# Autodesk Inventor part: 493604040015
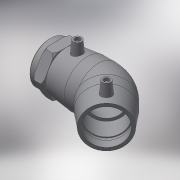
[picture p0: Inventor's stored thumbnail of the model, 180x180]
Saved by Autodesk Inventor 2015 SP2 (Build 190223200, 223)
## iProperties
Created: 2017-06
Part Number: 493604040015
Material: Generic
Description: PLASSON 45° ELBOW TRANSITION FEMALE 40-1.1/2"
Document SubType Name: Modeling
Designer: KIM
Mass: 179.754 g
Surface Area: 478.427 cm^2
Volume: 179.754 cm^3
Density: 1 g/cm^3
Appearance: Default
Author: KIM
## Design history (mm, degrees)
derived "493604.ipt"
feature "Solid1::493604.ipt"
tag "TaggingFeature1"
body "Solid1"
other parameters: "d2" = 56, "d4" = 27, "d5" = 50.4, "d8" = 168 deg, "d10" = 17.6, "d11" = 5.86667, "d29" = 47, "d30" = 15, "d31" = 37.8, "d34" = 5 deg, "d41" = 4, "d42" = 14, "d43" = 0, "d50" = 34, "d51" = 17.6, "d52" = 44, "d54" = 135 deg, "d86" = 25.2, "d87" = 135 deg, "d88" = 108, "d90" = 44, "d91" = 0, "d92" = 44, "d93" = 0, "d101" = 3, "d102" = 0, "d107" = 0.1, "d108" = 29, "d110" = 25, "d112" = 56, "d113" = 44.845, "d114" = 22.5, "d128" = 15, "d129" = 0, "d132" = 2, "d133" = 45 deg, "d134" = 45 deg, "d136" = 1.2, "L_" = 133, "L_1" = 44, "D_" = 29, "A_" = 47, "d_2" = 12, "L_2" = 25, "Rp_" = 44.845, "D_1" = 56
